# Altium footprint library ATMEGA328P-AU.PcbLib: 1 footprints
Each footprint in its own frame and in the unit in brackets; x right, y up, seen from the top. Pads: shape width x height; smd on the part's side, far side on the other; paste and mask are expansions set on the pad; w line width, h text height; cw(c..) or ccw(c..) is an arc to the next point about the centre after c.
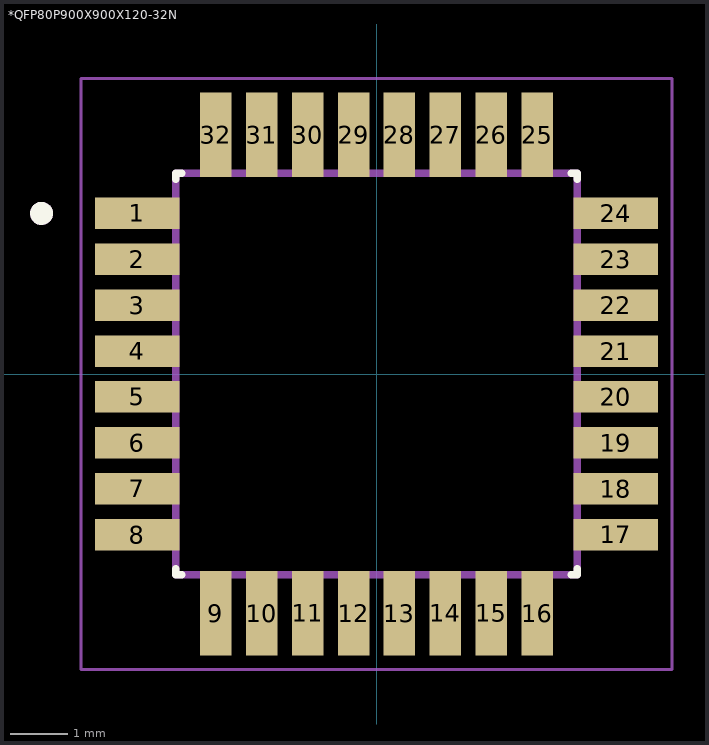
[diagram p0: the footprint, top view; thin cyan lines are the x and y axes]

## *QFP80P900X900X120-32N [mm]
pads (32):
  rect 1.47x0.55 smd: 1(-4.17,2.8) 2(-4.17,2) 3(-4.17,1.2) 4(-4.17,0.4) 5(-4.17,-0.4) 6(-4.17,-1.2) 7(-4.17,-2) 8(-4.17,-2.8) 17(4.17,-2.8) 18(4.17,-2) 19(4.17,-1.2) 20(4.17,-0.4) 21(4.17,0.4) 22(4.17,1.2) 23(4.17,2) 24(4.17,2.8)
  rect 0.55x1.47 smd: 9(-2.8,-4.17) 10(-2,-4.17) 11(-1.2,-4.17) 12(-0.4,-4.17) 13(0.4,-4.17) 14(1.2,-4.17) 15(2,-4.17) 16(2.8,-4.17) 25(2.8,4.17) 26(2,4.17) 27(1.2,4.17) 28(0.4,4.17) 29(-0.4,4.17) 30(-1.2,4.17) 31(-2,4.17) 32(-2.8,4.17)
Top Overlay:
  circle w0.2: c-5.84,2.8 r0.1
  lines w0.127: -3.5,-3.395 -3.5,-3.5 -3.395,-3.5 ; -3.5,3.395 -3.5,3.5 -3.395,3.5 ; 3.395,-3.5 3.5,-3.5 3.5,-3.395 ; 3.395,3.5 3.5,3.5 3.5,3.395
Mechanical 4:
  circle w0.2: c-5.84,2.8 r0.1
  circle w0.2: c-5.84,2.8 r0.1
  lines w0.127: -3.5,-3.5 -3.5,3.5 ; -3.5,-3.5 3.5,-3.5 ; -3.5,-3.5 -3.5,3.5 ; -3.5,-3.5 3.5,-3.5 ; -3.5,3.5 3.5,3.5 ; -3.5,3.5 3.5,3.5 ; 3.5,-3.5 3.5,3.5 ; 3.5,-3.5 3.5,3.5
Mechanical 16:
  lines w0.05: -5.155,-5.155 -5.155,5.155 5.155,5.155 5.155,-5.155 -5.155,-5.155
